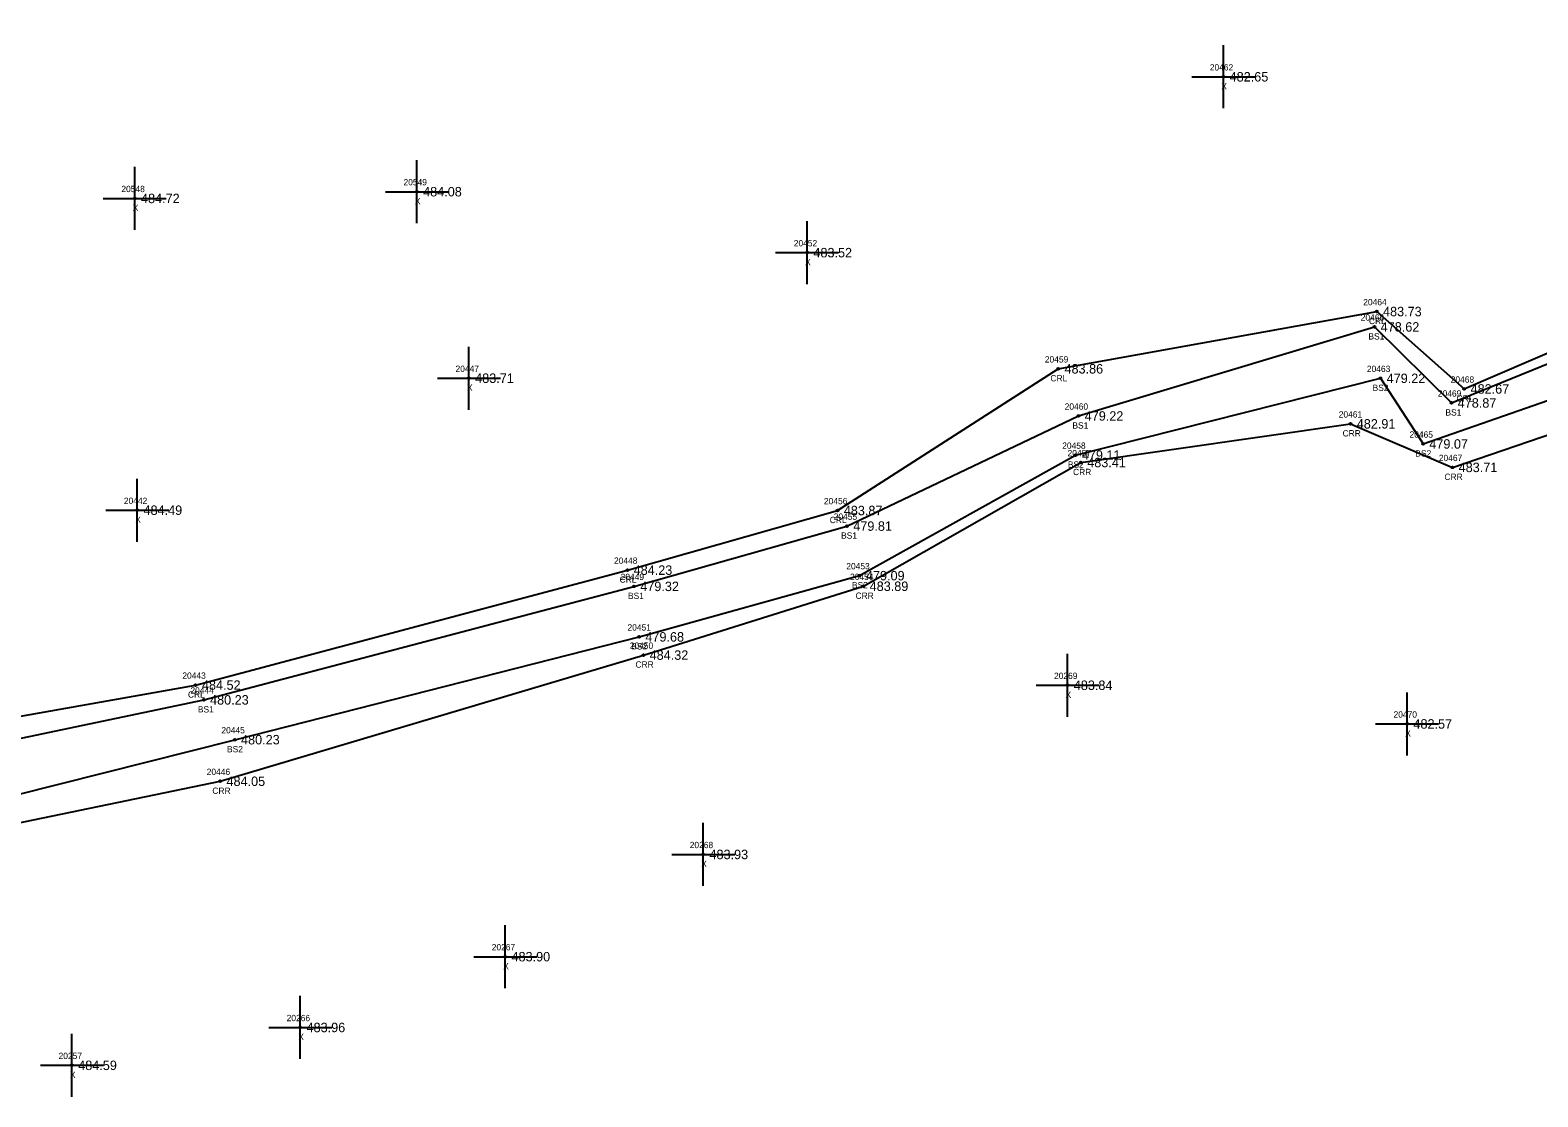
# Model space of a CAD drawing. Extents: x 1649406 to 1650436, y 896752 to 898178.
# Drawn here: x 1649970.8 to 1650210.2, y 897409.8 to 897579.1 of the extents above; entities that cross this region are included whole.
import ezdxf

# ---------------------------------------------------------------- set-up
doc = ezdxf.new("R2010")
doc.units = 0
for name, color, linetype in [('RD_DTM_BkLn2', 7, 'Continuous'), ('RD_DTM_BkLn_txCode', 7, 'Continuous'), ('RD_EX_H2O', 7, 'Continuous'), ('RD_EX_H2O_txCode', 7, 'Continuous'), ('RD_EX_Misc', 7, 'Continuous'), ('RD_EX_Misc_txCode', 7, 'Continuous'), ('RD_EX_TX_H2O_ELEV', 7, 'Continuous'), ('RD_EX_TX_Misc_ELEV', 7, 'Continuous'), ('RD_SMD_Locator', 7, 'Continuous')]:
    doc.layers.add(name, color=color, linetype=linetype)

msp = doc.modelspace()

# ---------------------------------------------------------------- linework, layer by layer
at = {"layer": 'RD_DTM_BkLn2'}
for points in [[(1649873.21, 897436.53), (1649903.52, 897432.72), (1649919.05, 897445.43), (1649948.16, 897462.25), (1649998.36, 897472.78), (1650066.66, 897490.8), (1650100.48, 897500.37), (1650137.22, 897517.85), (1650184.21, 897531.99), (1650196.44, 897519.92), (1650247.18, 897540.57), (1650293.31, 897540.96), (1650345.63, 897555.71), (1650381.77, 897576.92), (1650384.86, 897569.3), (1650418.68, 897572.17)], [(1649870.24, 897429.91), (1649900.86, 897426.65), (1649924.89, 897441.29), (1649954.5, 897454.17), (1650003.28, 897466.46), (1650067.47, 897482.78), (1650102.49, 897492.5), (1650136.77, 897511.64), (1650185.16, 897523.83), (1650191.93, 897513.41), (1650246.64, 897532.49), (1650295.05, 897532.6), (1650346.56, 897548.17), (1650378.24, 897567.88), (1650382.5, 897562.26), (1650420.79, 897565.67)]]:
    msp.add_lwpolyline(points, dxfattribs=at)
at = {"layer": 'RD_EX_H2O'}
for points in [[(1649876.68, 897438.74), (1649903.57, 897434.32), (1649917.97, 897448.25), (1649945.97, 897466.05), (1649997.07, 897475.13), (1650065.61, 897493.38), (1650098.97, 897502.84), (1650134.01, 897525.34), (1650184.58, 897534.43), (1650198.48, 897522.14), (1650246.85, 897542.98), (1650292.7, 897543.66), (1650345.21, 897558.55), (1650381.85, 897579.1), (1650386.65, 897572.92), (1650418.93, 897577.14)], [(1649868.27, 897424.7), (1649897.36, 897423.62), (1649925.96, 897437.78), (1649956.47, 897450.69), (1650000.97, 897459.86), (1650068.15, 897479.89), (1650103.08, 897490.82), (1650137.62, 897510.46), (1650180.41, 897516.6), (1650196.59, 897509.69), (1650246.91, 897526.88), (1650295.53, 897529.67), (1650347.35, 897546.47), (1650373.21, 897562.26), (1650385.6, 897559.55), (1650420.39, 897565.14)]]:
    msp.add_lwpolyline(points, dxfattribs=at)
at = {"layer": 'RD_EX_Misc'}
for p, q in [((1650160.23, 897566.7), (1650160.23, 897576.7)), ((1650155.23, 897571.7), (1650165.23, 897571.7)), ((1650032.19, 897548.46), (1650032.19, 897558.46)), ((1649987.4, 897547.39), (1649987.4, 897557.39)), ((1650027.19, 897553.46), (1650037.19, 897553.46)), ((1649982.4, 897552.39), (1649992.4, 897552.39)), ((1650094.15, 897538.78), (1650094.15, 897548.78)), ((1650089.15, 897543.78), (1650099.15, 897543.78)), ((1650040.45, 897518.85), (1650040.45, 897528.85)), ((1650035.45, 897523.85), (1650045.45, 897523.85)), ((1649987.8, 897497.89), (1649987.8, 897507.89)), ((1649982.8, 897502.89), (1649992.8, 897502.89)), ((1650135.49, 897470.1), (1650135.49, 897480.1)), ((1650130.49, 897475.1), (1650140.49, 897475.1)), ((1650189.41, 897463.96), (1650189.41, 897473.96)), ((1650184.41, 897468.96), (1650194.41, 897468.96)), ((1650077.65, 897443.24), (1650077.65, 897453.24)), ((1650072.65, 897448.24), (1650082.65, 897448.24)), ((1650046.22, 897427.01), (1650046.22, 897437.01)), ((1650041.22, 897432.01), (1650051.22, 897432.01)), ((1650013.68, 897415.77), (1650013.68, 897425.77)), ((1649977.43, 897409.76), (1649977.43, 897419.76)), ((1650008.68, 897420.77), (1650018.68, 897420.77)), ((1649972.43, 897414.76), (1649982.43, 897414.76))]:
    msp.add_line(p, q, dxfattribs=at)
at = {"layer": 'RD_SMD_Locator'}
for centre in [(1650160.23, 897571.7), (1650032.19, 897553.46), (1649987.4, 897552.39), (1650094.15, 897543.78), (1650184.58, 897534.43), (1650184.21, 897531.99), (1650040.45, 897523.85), (1650134.01, 897525.34), (1650185.16, 897523.83), (1650198.48, 897522.14), (1650196.44, 897519.92), (1650137.22, 897517.85), (1650180.41, 897516.6), (1650191.93, 897513.41), (1650136.77, 897511.64), (1650137.62, 897510.46), (1650196.59, 897509.69), (1649987.8, 897502.89), (1650098.97, 897502.84), (1650100.48, 897500.37), (1650065.61, 897493.38), (1650066.66, 897490.8), (1650102.49, 897492.5), (1650103.08, 897490.82), (1650067.47, 897482.78), (1650068.15, 897479.89), (1649997.07, 897475.13), (1650135.49, 897475.1), (1649998.36, 897472.78), (1650189.41, 897468.96), (1650003.28, 897466.46), (1650000.97, 897459.86), (1650077.65, 897448.24), (1650046.22, 897432.01), (1650013.68, 897420.77), (1649977.43, 897414.76)]:
    msp.add_circle(centre, 0.15, dxfattribs=at)

# ---------------------------------------------------------------- texts
at = {"layer": 'RD_DTM_BkLn_txCode'}
for s, p in [('20466', (1650182.04, 897532.99)), ('BS1', (1650183.26, 897529.99)), ('20463', (1650183.02, 897524.83)), ('BS2', (1650183.93, 897521.83)), ('20469', (1650194.29, 897520.92)), ('20460', (1650135.04, 897518.85)), ('BS1', (1650136.27, 897515.85)), ('BS1', (1650195.49, 897517.92)), ('20465', (1650189.79, 897514.41)), ('20458', (1650134.65, 897512.64)), ('BS2', (1650190.71, 897511.41)), ('BS2', (1650135.54, 897509.64)), ('20455', (1650098.37, 897501.37)), ('BS1', (1650099.54, 897498.37)), ('20453', (1650100.37, 897493.5)), ('20449', (1650064.54, 897491.8)), ('BS2', (1650101.26, 897490.5)), ('BS1', (1650065.71, 897488.8)), ('20451', (1650065.63, 897483.78)), ('BS2', (1650066.24, 897480.78)), ('20444', (1649996.24, 897473.78)), ('BS1', (1649997.42, 897470.78)), ('20445', (1650001.16, 897467.46)), ('BS2', (1650002.05, 897464.46))]:
    msp.add_text(s, height=1, dxfattribs=at).set_placement(p)
at = {"layer": 'RD_EX_H2O_txCode'}
for s, p in [('20464', (1650182.44, 897535.43)), ('CRL', (1650183.35, 897532.43)), ('20459', (1650131.89, 897526.34)), ('CRL', (1650132.78, 897523.34)), ('20468', (1650196.33, 897523.14)), ('CRL', (1650197.25, 897520.14)), ('20461', (1650178.55, 897517.6)), ('CRR', (1650179.16, 897514.6)), ('20457', (1650135.5, 897511.46)), ('20467', (1650194.44, 897510.69)), ('CRR', (1650136.37, 897508.46)), ('CRR', (1650195.33, 897507.69)), ('20456', (1650096.82, 897503.84)), ('CRL', (1650097.74, 897500.84)), ('20448', (1650063.49, 897494.38)), ('CRL', (1650064.38, 897491.38)), ('20454', (1650100.97, 897491.82)), ('CRR', (1650101.83, 897488.82)), ('20450', (1650065.99, 897480.89)), ('CRR', (1650066.9, 897477.89)), ('20443', (1649994.96, 897476.13)), ('CRL', (1649995.85, 897473.13)), ('20446', (1649998.83, 897460.86)), ('CRR', (1649999.72, 897457.86))]:
    msp.add_text(s, height=1, dxfattribs=at).set_placement(p)
at = {"layer": 'RD_EX_Misc_txCode'}
for s, p in [('20462', (1650158.08, 897572.7)), ('X', (1650159.91, 897569.7)), ('20549', (1650030.07, 897554.46)), ('20548', (1649985.28, 897553.39)), ('X', (1649987.08, 897550.39)), ('X', (1650031.87, 897551.46)), ('20452', (1650092.03, 897544.78)), ('X', (1650093.83, 897541.78)), ('20447', (1650038.33, 897524.85)), ('X', (1650040.14, 897521.85)), ('20442', (1649985.68, 897503.89)), ('X', (1649987.49, 897500.89)), ('20269', (1650133.35, 897476.1)), ('X', (1650135.18, 897473.1)), ('20470', (1650187.25, 897469.96)), ('X', (1650189.1, 897466.96)), ('20268', (1650075.51, 897449.24)), ('X', (1650077.33, 897446.24)), ('20267', (1650044.08, 897433.01)), ('X', (1650045.9, 897430.01)), ('20266', (1650011.52, 897421.77)), ('X', (1650013.37, 897418.77)), ('20257', (1649975.31, 897415.76)), ('X', (1649977.11, 897412.76))]:
    msp.add_text(s, height=1, dxfattribs=at).set_placement(p)
at = {"layer": 'RD_EX_TX_H2O_ELEV'}
for s, p in [('483.73', (1650185.58, 897533.68)), ('483.86', (1650135.01, 897524.59)), ('482.67', (1650199.48, 897521.39)), ('482.91', (1650181.41, 897515.85)), ('483.41', (1650138.62, 897509.71)), ('483.71', (1650197.59, 897508.94)), ('483.87', (1650099.97, 897502.09)), ('484.23', (1650066.61, 897492.63)), ('483.89', (1650104.08, 897490.07)), ('484.32', (1650069.15, 897479.14)), ('484.52', (1649998.07, 897474.38)), ('484.05', (1650001.97, 897459.11))]:
    msp.add_text(s, height=1.5, dxfattribs=at).set_placement(p)
at = {"layer": 'RD_EX_TX_Misc_ELEV'}
for s, p in [('482.65', (1650161.23, 897570.95)), ('484.72', (1649988.4, 897551.64)), ('484.08', (1650033.19, 897552.71)), ('483.52', (1650095.15, 897543.03)), ('478.62', (1650185.21, 897531.24)), ('483.71', (1650041.45, 897523.1)), ('479.22', (1650186.16, 897523.08)), ('478.87', (1650197.44, 897519.17)), ('479.22', (1650138.22, 897517.1)), ('479.11', (1650137.77, 897510.89)), ('479.07', (1650192.93, 897512.66)), ('484.49', (1649988.8, 897502.14)), ('479.81', (1650101.48, 897499.62)), ('479.09', (1650103.49, 897491.75)), ('479.32', (1650067.66, 897490.05)), ('479.68', (1650068.47, 897482.03)), ('483.84', (1650136.49, 897474.35)), ('480.23', (1649999.36, 897472.03)), ('482.57', (1650190.41, 897468.21)), ('480.23', (1650004.28, 897465.71)), ('483.93', (1650078.65, 897447.49)), ('483.90', (1650047.22, 897431.26)), ('483.96', (1650014.68, 897420.02)), ('484.59', (1649978.43, 897414.01))]:
    msp.add_text(s, height=1.5, dxfattribs=at).set_placement(p)

doc.saveas('drawing.dxf')
